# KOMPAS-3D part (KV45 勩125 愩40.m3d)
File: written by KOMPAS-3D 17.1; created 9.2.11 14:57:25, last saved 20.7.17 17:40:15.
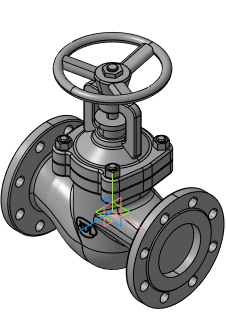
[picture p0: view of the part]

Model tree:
1. Плоскость XY
2. Плоскость ZX
3. Плоскость ZY
4. Ось X
5. Ось Y
6. Ось Z
7. Начало координат
8. Операция без истории:3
